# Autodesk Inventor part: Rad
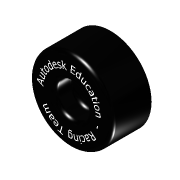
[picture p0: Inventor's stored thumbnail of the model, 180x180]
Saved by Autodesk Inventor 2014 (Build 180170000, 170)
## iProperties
Created: 2013-01
Part Number: Rad
Material: ABS Plastic
Document SubType Name: Modeling
Designer: banachd
Density: 1 g/cm^3
Description: 30 mm DIA x 15 mm WHEEL
Appearance: Schwarz
Author: banachd
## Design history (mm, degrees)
sketch "Skizze1"
  geometry: L1 (0, 0)-(0, -7); L2 (0, -7)-(6, -7); L3 (6, -7)-(6, -14.75); L4 (15, -14.75)-(15, 0); L5 (15, 0)-(0, 0); L6 (6, -14.75)-(15, -14.75); A1 r 40.625 centre (10.5, 25.625) between (6, -14.75) and (15, -14.75)
  constraints: 12 end point, 4 parallel, 3 point on circle, 1 centre point, 1 horizontal alignment, 1 perpendicular, 1 vertical
  dimensions: "d2" = 30 diameter of L4 L1; "d4" = 12 diameter of L3 L1; "d5" = 15 distance edge to line of A1 L5; "d6" = 0.25 distance edge to line of A1 L6; "d7" = 7 distance of L1.start L1.end
revolve "Revolution1" sketch "Skizze1" stored, may be unused: angle "d8" = 90 deg
hole "Hole1" diameter "d11" = 3; stored, may be unused: countersink angle "d15" = 90 deg, drill point angle "d17" = 118 deg; dims "d9" = 10, "d10" = 10, "d12" = 6, "d13" = 4, "d14" = 2, "d16" = 8
fillet "Fillet1" dims "d18" = 2
workplane "Work Plane1"
shell "Shell1" dims "d19" = 1
sketch "Skizze2"
  geometry: C1 r 9.5 at (0, 0); 1 further point
  constraints: 1 centre point, 1 coincident, 1 other
  dimensions: "d21" = 19 diameter of C1
emboss "Emboss1" sketch "Skizze2" dims "d2" = 30, "d23" = 0.1, "d24" = 0
body "Solid1"
other parameters: "d20" = -15
